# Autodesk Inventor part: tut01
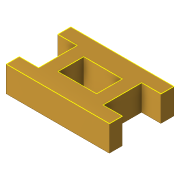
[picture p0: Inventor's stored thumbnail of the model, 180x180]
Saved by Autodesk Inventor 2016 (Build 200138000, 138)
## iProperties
Created: 2015-02
Part Number: tut01
Material: Brass, Soft Yellow
Document SubType Name: Modeling
Designer: Sandeep
Density: 8.47 g/cm^3
Appearance: Brass - Satin
Author: Sandeep
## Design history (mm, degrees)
sketch "Sketch1"
  geometry: L1 (-80, 0)-(0, 0); L2 (0, 0)-(0, 10); L3 (0, 10)-(-15, 10); L4 (-15, 10)-(-15, 40); L5 (-15, 40)-(0, 40); L6 (0, 40)-(0, 50); L7 (0, 50)-(-80, 50); L8 (-80, 50)-(-80, 40); L9 (-80, 40)-(-65, 40); L10 (-65, 40)-(-65, 10); L11 (-65, 10)-(-80, 10); L12 (-80, 0)-(-80, 10); L13 (-25, 35)-(-55, 35); L14 (-55, 35)-(-55, 15); L15 (-55, 15)-(-25, 15); L16 (-25, 15)-(-25, 35); 1 further point
  constraints: 32 end point, 9 perpendicular, 7 point on line, 2 collinear, 2 horizontal, 2 parallel, 1 coincident
  dimensions: "d0" = 80 distance of L1.start L1.end; "d1" = 10 distance of L1.end L2.end; "d2" = 30 distance of L3.end L4.end; "d3" = 20 distance of L13.end L14.end; "d4" = 30 distance of L13.start L13.end; "d5" = 10 distance between parallel lines of L4 L16; "d6" = 10 distance between parallel lines of L10 L14; "d7" = 15 distance between parallel lines of L1 L15
extrude "Extrusion1" new body sketch "Sketch1" distance "d8" = 20; taper "d9" = 0 deg
sketch "Sketch2"
  geometry: L1 (-25, 35)-(-25, 15) reference; L2 (-25, 15)-(-55, 15) reference; L3 (-55, 15)-(-55, 35) reference; L4 (-55, 35)-(-25, 35) reference; L5 (-80, 0)-(0, 0) reference; L6 (0, 0)-(0, 10) reference; L7 (0, 10)-(-15, 10) reference; L8 (-15, 10)-(-15, 40) reference; L9 (-15, 40)-(0, 40) reference; L10 (0, 40)-(0, 50) reference; L11 (0, 50)-(-80, 50) reference; L12 (-80, 50)-(-80, 40) reference; L13 (-80, 40)-(-65, 40) reference; L14 (-65, 40)-(-65, 10) reference; L15 (-65, 10)-(-80, 10) reference; L16 (-80, 10)-(-80, 0) reference
body "Solid1"
